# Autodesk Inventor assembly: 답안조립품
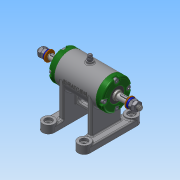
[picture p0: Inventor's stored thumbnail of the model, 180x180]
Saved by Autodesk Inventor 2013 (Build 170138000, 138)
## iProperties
Created: 2015-11
Part Number: 답안조립품
Document SubType Name: Assembly
Designer: ST3
Author: ST3
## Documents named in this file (16)
- C:\Users\ST3\Desktop\451109V1011\답안조립품.iam
- C:\Users\ST3\Desktop\451109V1011\V벨트풀리.ipt
- C:\Users\ST3\Desktop\451109V1011\너트 M 8.ipt
- C:\Users\ST3\Desktop\451109V1011\니플 M 6 x 0.75.ipt
- C:\Users\ST3\Desktop\451109V1011\답안본체.ipt
- C:\Users\ST3\Desktop\451109V1011\베어링 15 x 32 x 9.ipt
- C:\Users\ST3\Desktop\451109V1011\볼트 M 6 x 8.ipt
- C:\Users\ST3\Desktop\451109V1011\볼트 M4 x 12.ipt
- C:\Users\ST3\Desktop\451109V1011\스퍼기어.ipt
- C:\Users\ST3\Desktop\451109V1011\스프링와셔 8.ipt
- C:\Users\ST3\Desktop\451109V1011\오일 실 15 25 7.ipt
- C:\Users\ST3\Desktop\451109V1011\와셔 6x11.5.ipt
- C:\Users\ST3\Desktop\451109V1011\와셔 8x17.ipt
- C:\Users\ST3\Desktop\451109V1011\축.ipt
- C:\Users\ST3\Desktop\451109V1011\커버.ipt
- C:\Users\ST3\Desktop\451109V1011\키 3 x 3 x 12.ipt
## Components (11 placed, 3 different names)
1. V벨트풀리:1
2. KS B 2023 6002 - 15 x 32 x 9:1
3. ISO 4762 M4 x 12:1
4. KS B 2023 6002 - 15 x 32 x 9:2
5. ISO 4762 M4 x 12:2
6. ISO 4762 M4 x 12:3
7. ISO 4762 M4 x 12:4
8. ISO 4762 M4 x 12:5
9. ISO 4762 M4 x 12:6
10. ISO 4762 M4 x 12:7
11. ISO 4762 M4 x 12:8
